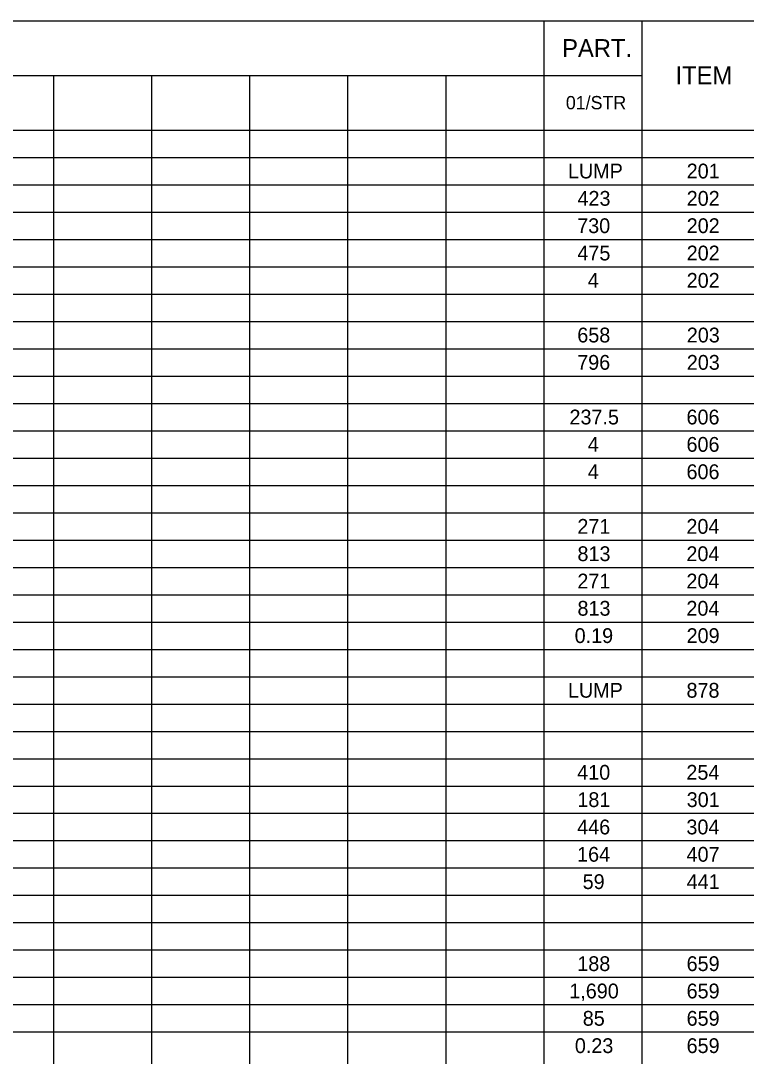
# Model space of a CAD drawing. Extents: x -98 to 34, y 0 to 58.
# Drawn here: x -89.98 to -82.55, y 47.24 to 57.85 of the extents above; entities that cross this region are included whole.
import ezdxf

# ---------------------------------------------------------------- set-up
doc = ezdxf.new("R2010")
doc.units = 0
doc.layers.add('Default', color=7, linetype='Continuous')

msp = doc.modelspace()

# ---------------------------------------------------------------- linework, layer by layer
at = {"layer": 'Default'}
for p, q in [((-97.686, 57.846), (-67.186, 57.846)), ((-84.626, 57.846), (-84.626, 36.848)), ((-83.621, 57.846), (-83.621, 36.848)), ((-97.686, 57.286), (-83.621, 57.286)), ((-89.649, 57.286), (-89.649, 36.848)), ((-88.644, 57.286), (-88.644, 36.848)), ((-87.64, 57.286), (-87.64, 36.848)), ((-86.635, 57.286), (-86.635, 36.848)), ((-85.63, 57.286), (-85.63, 36.848)), ((-97.686, 56.726), (-67.186, 56.726)), ((-97.686, 56.446), (-67.186, 56.446)), ((-97.686, 56.166), (-67.186, 56.166)), ((-97.686, 55.886), (-67.186, 55.886)), ((-97.686, 55.606), (-67.186, 55.606)), ((-97.686, 55.326), (-67.186, 55.326)), ((-97.686, 55.046), (-67.186, 55.046)), ((-97.686, 54.766), (-67.186, 54.766)), ((-97.686, 54.486), (-67.186, 54.486)), ((-97.686, 54.206), (-67.186, 54.206)), ((-97.686, 53.926), (-67.186, 53.926)), ((-97.686, 53.646), (-67.186, 53.646)), ((-97.686, 53.366), (-67.186, 53.366)), ((-97.686, 53.086), (-67.186, 53.086)), ((-97.686, 52.806), (-67.186, 52.806)), ((-97.686, 52.526), (-67.186, 52.526)), ((-97.686, 52.246), (-67.186, 52.246)), ((-97.686, 51.966), (-67.186, 51.966)), ((-97.686, 51.686), (-67.186, 51.686)), ((-97.686, 51.406), (-67.186, 51.406)), ((-97.686, 51.126), (-67.186, 51.126)), ((-97.686, 50.846), (-67.186, 50.846)), ((-97.686, 50.566), (-67.186, 50.566)), ((-97.686, 50.286), (-67.186, 50.286)), ((-97.686, 50.006), (-67.186, 50.006)), ((-97.686, 49.727), (-67.186, 49.727)), ((-97.686, 49.447), (-67.186, 49.447)), ((-97.686, 49.167), (-67.186, 49.167)), ((-97.686, 48.887), (-67.186, 48.887)), ((-97.686, 48.607), (-67.186, 48.607)), ((-97.686, 48.327), (-67.186, 48.327)), ((-97.686, 48.047), (-67.186, 48.047)), ((-97.686, 47.767), (-67.186, 47.767)), ((-97.686, 47.487), (-67.186, 47.487))]:
    msp.add_line(p, q, dxfattribs=at)

# ---------------------------------------------------------------- texts
for s, height, p in [('PART.', 0.1818, (-84.437, 57.475)), ('ITEM', 0.1818, (-83.275, 57.195)), ('01/STR', 0.1364, (-84.399, 56.938)), ('LUMP', 0.1515, (-84.378, 56.23)), ('201', 0.1515, (-83.161, 56.23)), ('423', 0.1515, (-84.28, 55.95)), ('202', 0.1515, (-83.161, 55.95)), ('730', 0.1515, (-84.283, 55.67)), ('202', 0.1515, (-83.161, 55.67)), ('475', 0.1515, (-84.281, 55.39)), ('202', 0.1515, (-83.161, 55.39)), ('4', 0.152, (-84.175, 55.11)), ('202', 0.1515, (-83.161, 55.11)), ('658', 0.1515, (-84.282, 54.55)), ('203', 0.1515, (-83.16, 54.55)), ('796', 0.1515, (-84.283, 54.27)), ('203', 0.1515, (-83.16, 54.27)), ('237.5', 0.1515, (-84.362, 53.71)), ('606', 0.1515, (-83.163, 53.71)), ('4', 0.152, (-84.175, 53.43)), ('606', 0.1515, (-83.163, 53.43)), ('4', 0.152, (-84.175, 53.15)), ('606', 0.1515, (-83.163, 53.15)), ('271', 0.1515, (-84.281, 52.59)), ('204', 0.1515, (-83.164, 52.59)), ('813', 0.1515, (-84.28, 52.31)), ('204', 0.1515, (-83.164, 52.31)), ('271', 0.1515, (-84.281, 52.03)), ('204', 0.1515, (-83.164, 52.03)), ('813', 0.1515, (-84.28, 51.751)), ('204', 0.1515, (-83.164, 51.751)), ('0.19', 0.1515, (-84.309, 51.471)), ('209', 0.1515, (-83.162, 51.471)), ('LUMP', 0.1515, (-84.378, 50.911)), ('878', 0.1515, (-83.163, 50.911)), ('410', 0.1515, (-84.283, 50.071)), ('254', 0.1515, (-83.164, 50.071)), ('181', 0.1515, (-84.281, 49.791)), ('301', 0.1515, (-83.161, 49.791)), ('446', 0.1515, (-84.283, 49.511)), ('304', 0.1515, (-83.164, 49.511)), ('164', 0.1515, (-84.284, 49.231)), ('407', 0.1515, (-83.162, 49.231)), ('59', 0.1515, (-84.227, 48.951)), ('441', 0.1515, (-83.161, 48.951)), ('188', 0.1515, (-84.282, 48.111)), ('659', 0.1515, (-83.162, 48.111)), ('1,690', 0.1515, (-84.364, 47.831)), ('659', 0.1515, (-83.162, 47.831)), ('85', 0.1515, (-84.226, 47.551)), ('659', 0.1515, (-83.162, 47.551)), ('0.23', 0.1515, (-84.307, 47.271)), ('659', 0.1515, (-83.162, 47.271))]:
    msp.add_text(s, height=height, dxfattribs=at).set_placement(p)

doc.saveas('drawing.dxf')
